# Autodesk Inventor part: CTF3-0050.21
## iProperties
Shininess: 64.0
Length Units: 11269
Angle Units: 11279
Time Units: 11290
Mass Units: 11283
Length Display Precision: 3
Angle Display Precision: 2
Compacted: True
Part Number: CTF3-0050.21
Document SubType Name: Modeling
Created: 2004-01
Designer: Lollo
Density: 0.0
Volumn: 0.0
Area: 0.0
PropertySet Name: Model Information
Control State: 0
Master: False
Checked Out: False
Author: Lollo
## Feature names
1. Estrusione1 [Extrusion]
2. Foro1 [Hole]
3. Smusso1 [Chamfer]
4. Smusso2 [Chamfer]
5. Smusso3 [Chamfer]
